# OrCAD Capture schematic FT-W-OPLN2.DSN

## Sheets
1 INDEX: size A; title: INDEX; rev: 1.0; note: ?
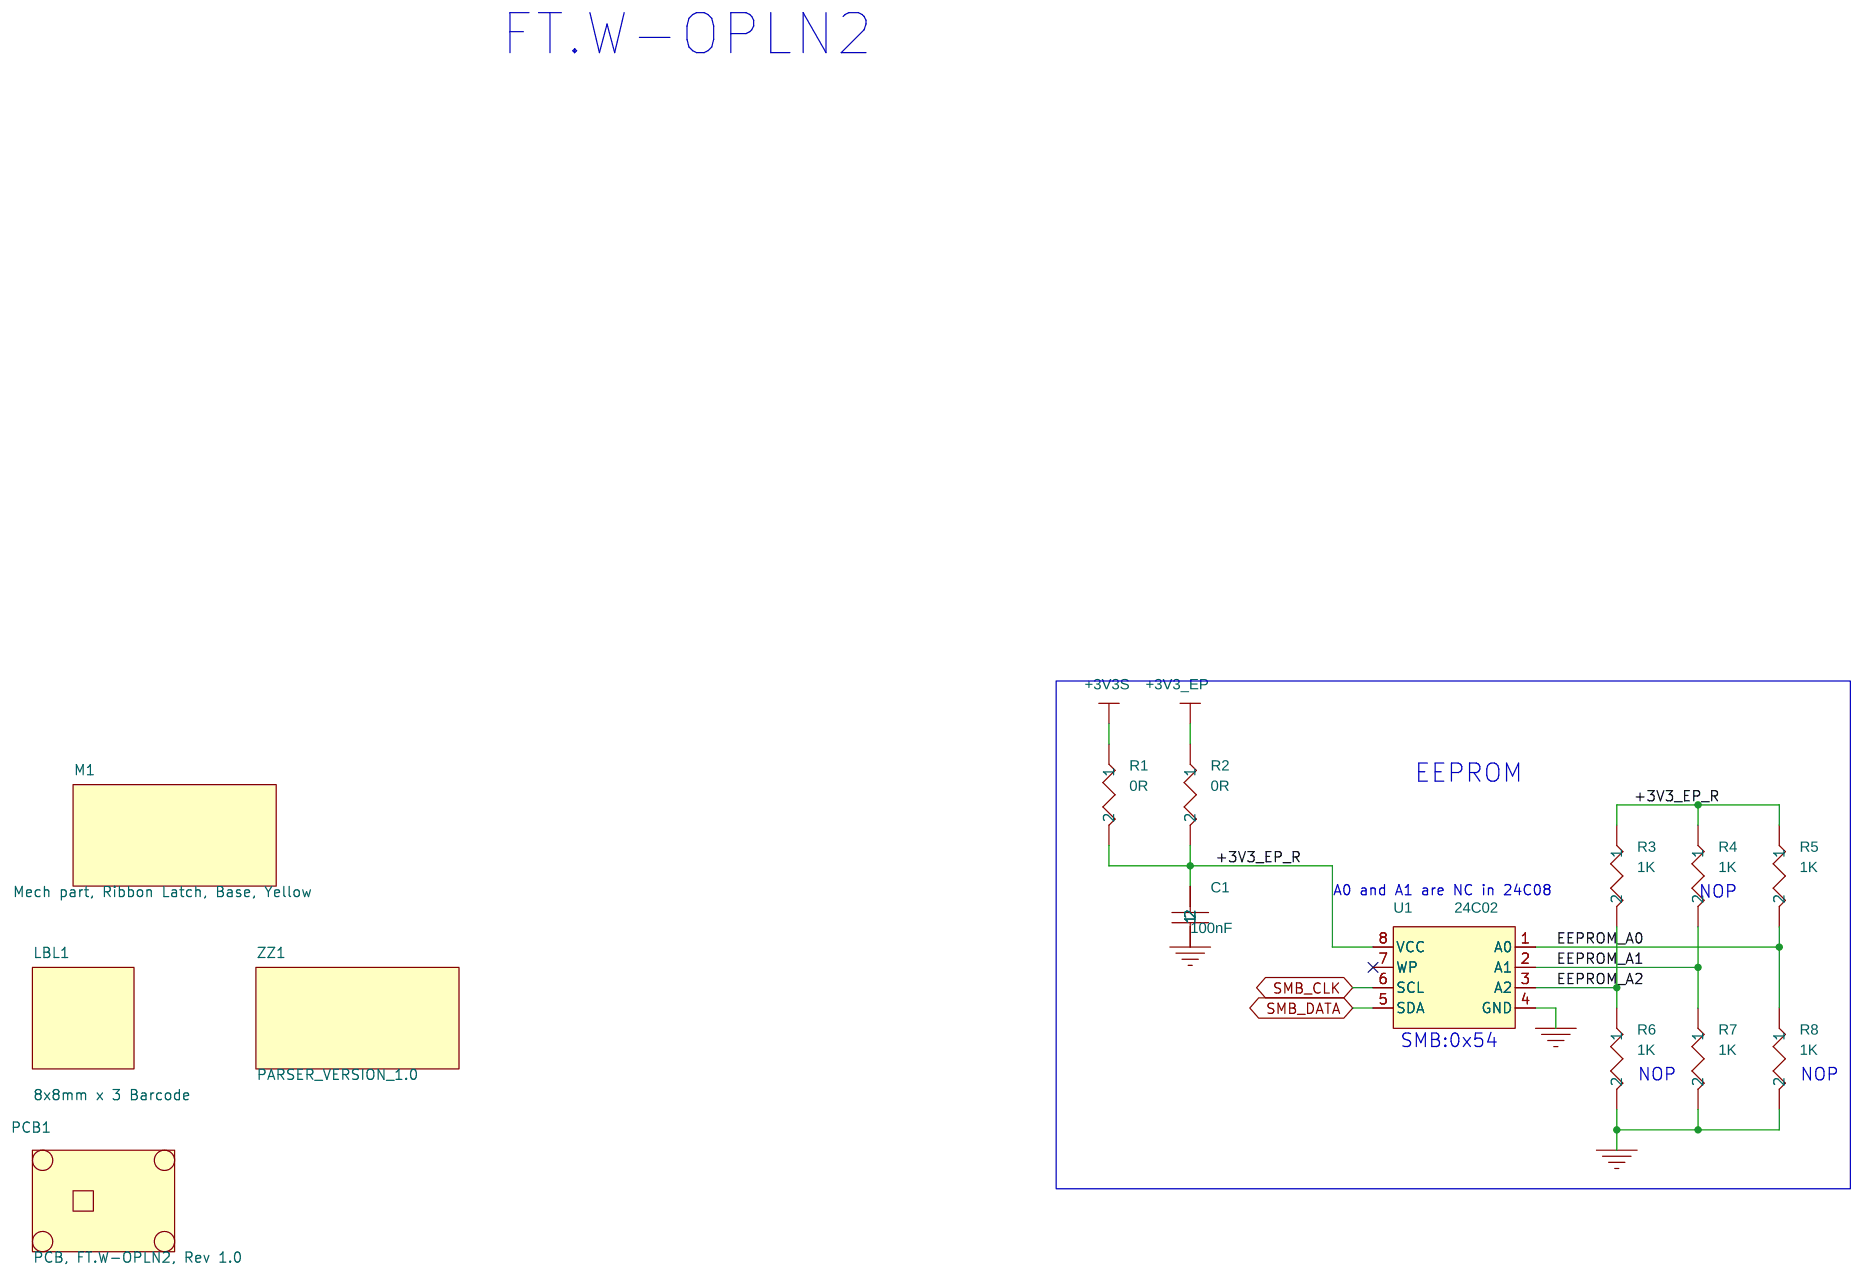
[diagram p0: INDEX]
2 Ribbon Conn.: size B; title: Ribbon Conn
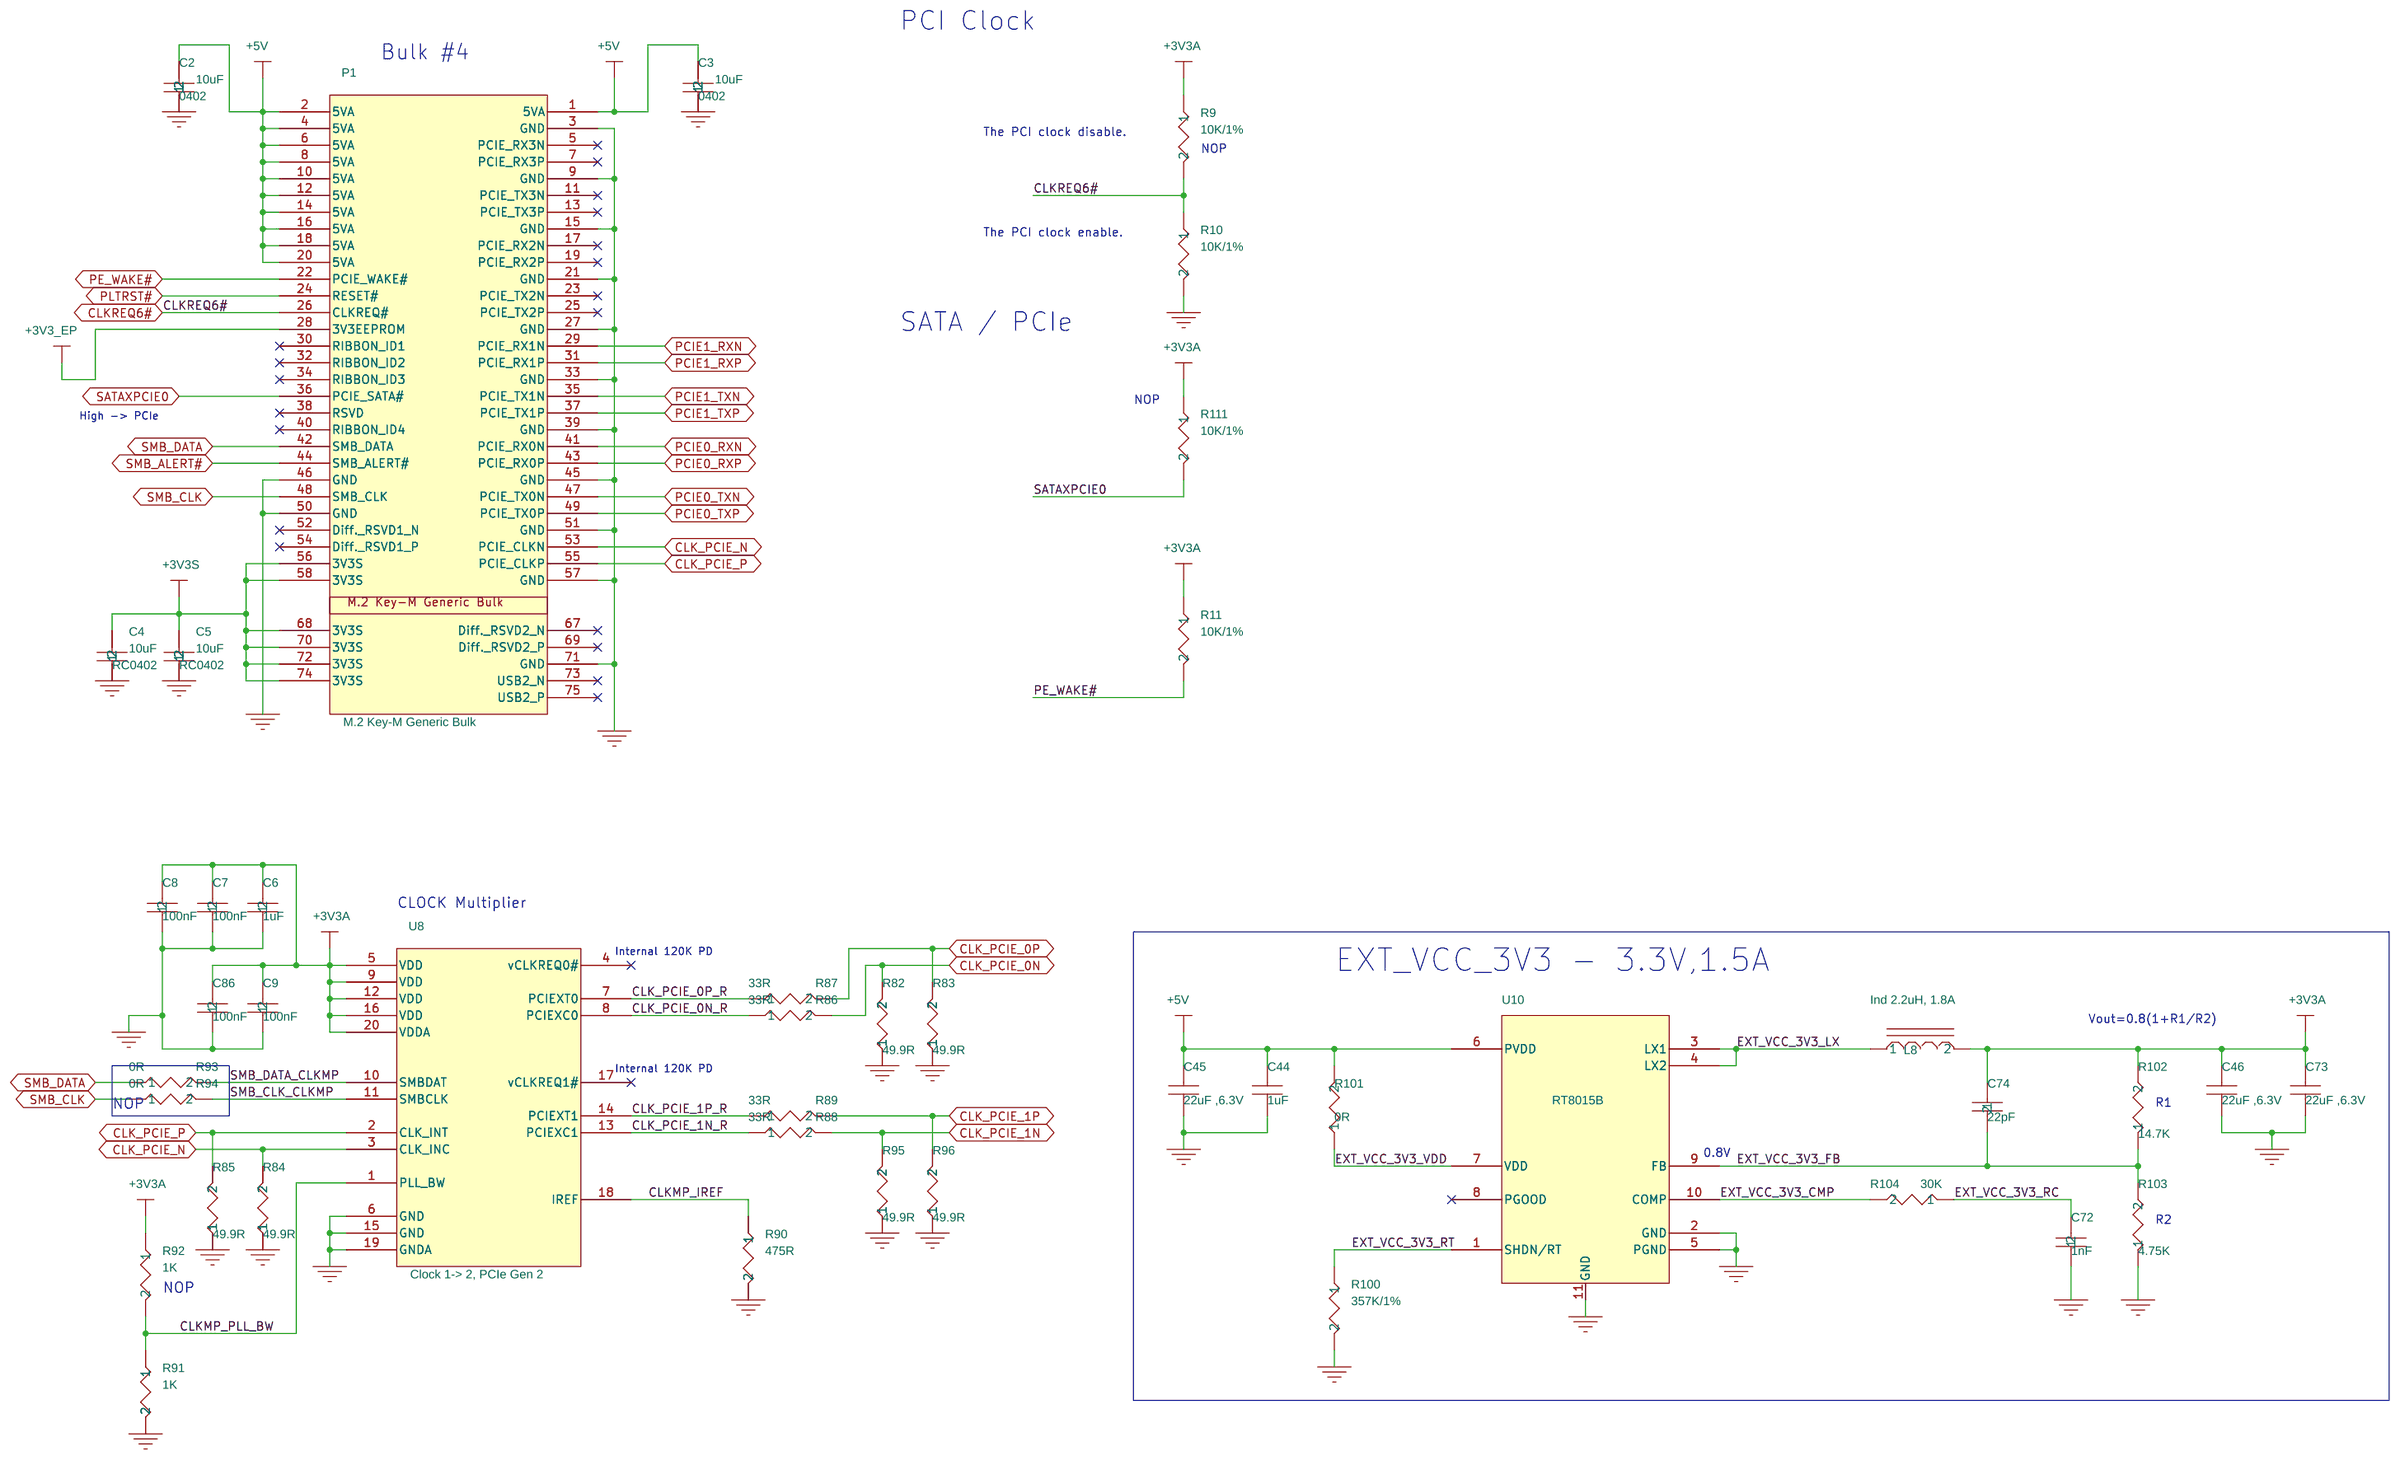
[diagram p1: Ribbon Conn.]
3 OPLN1: size Custom; title: OPLN1
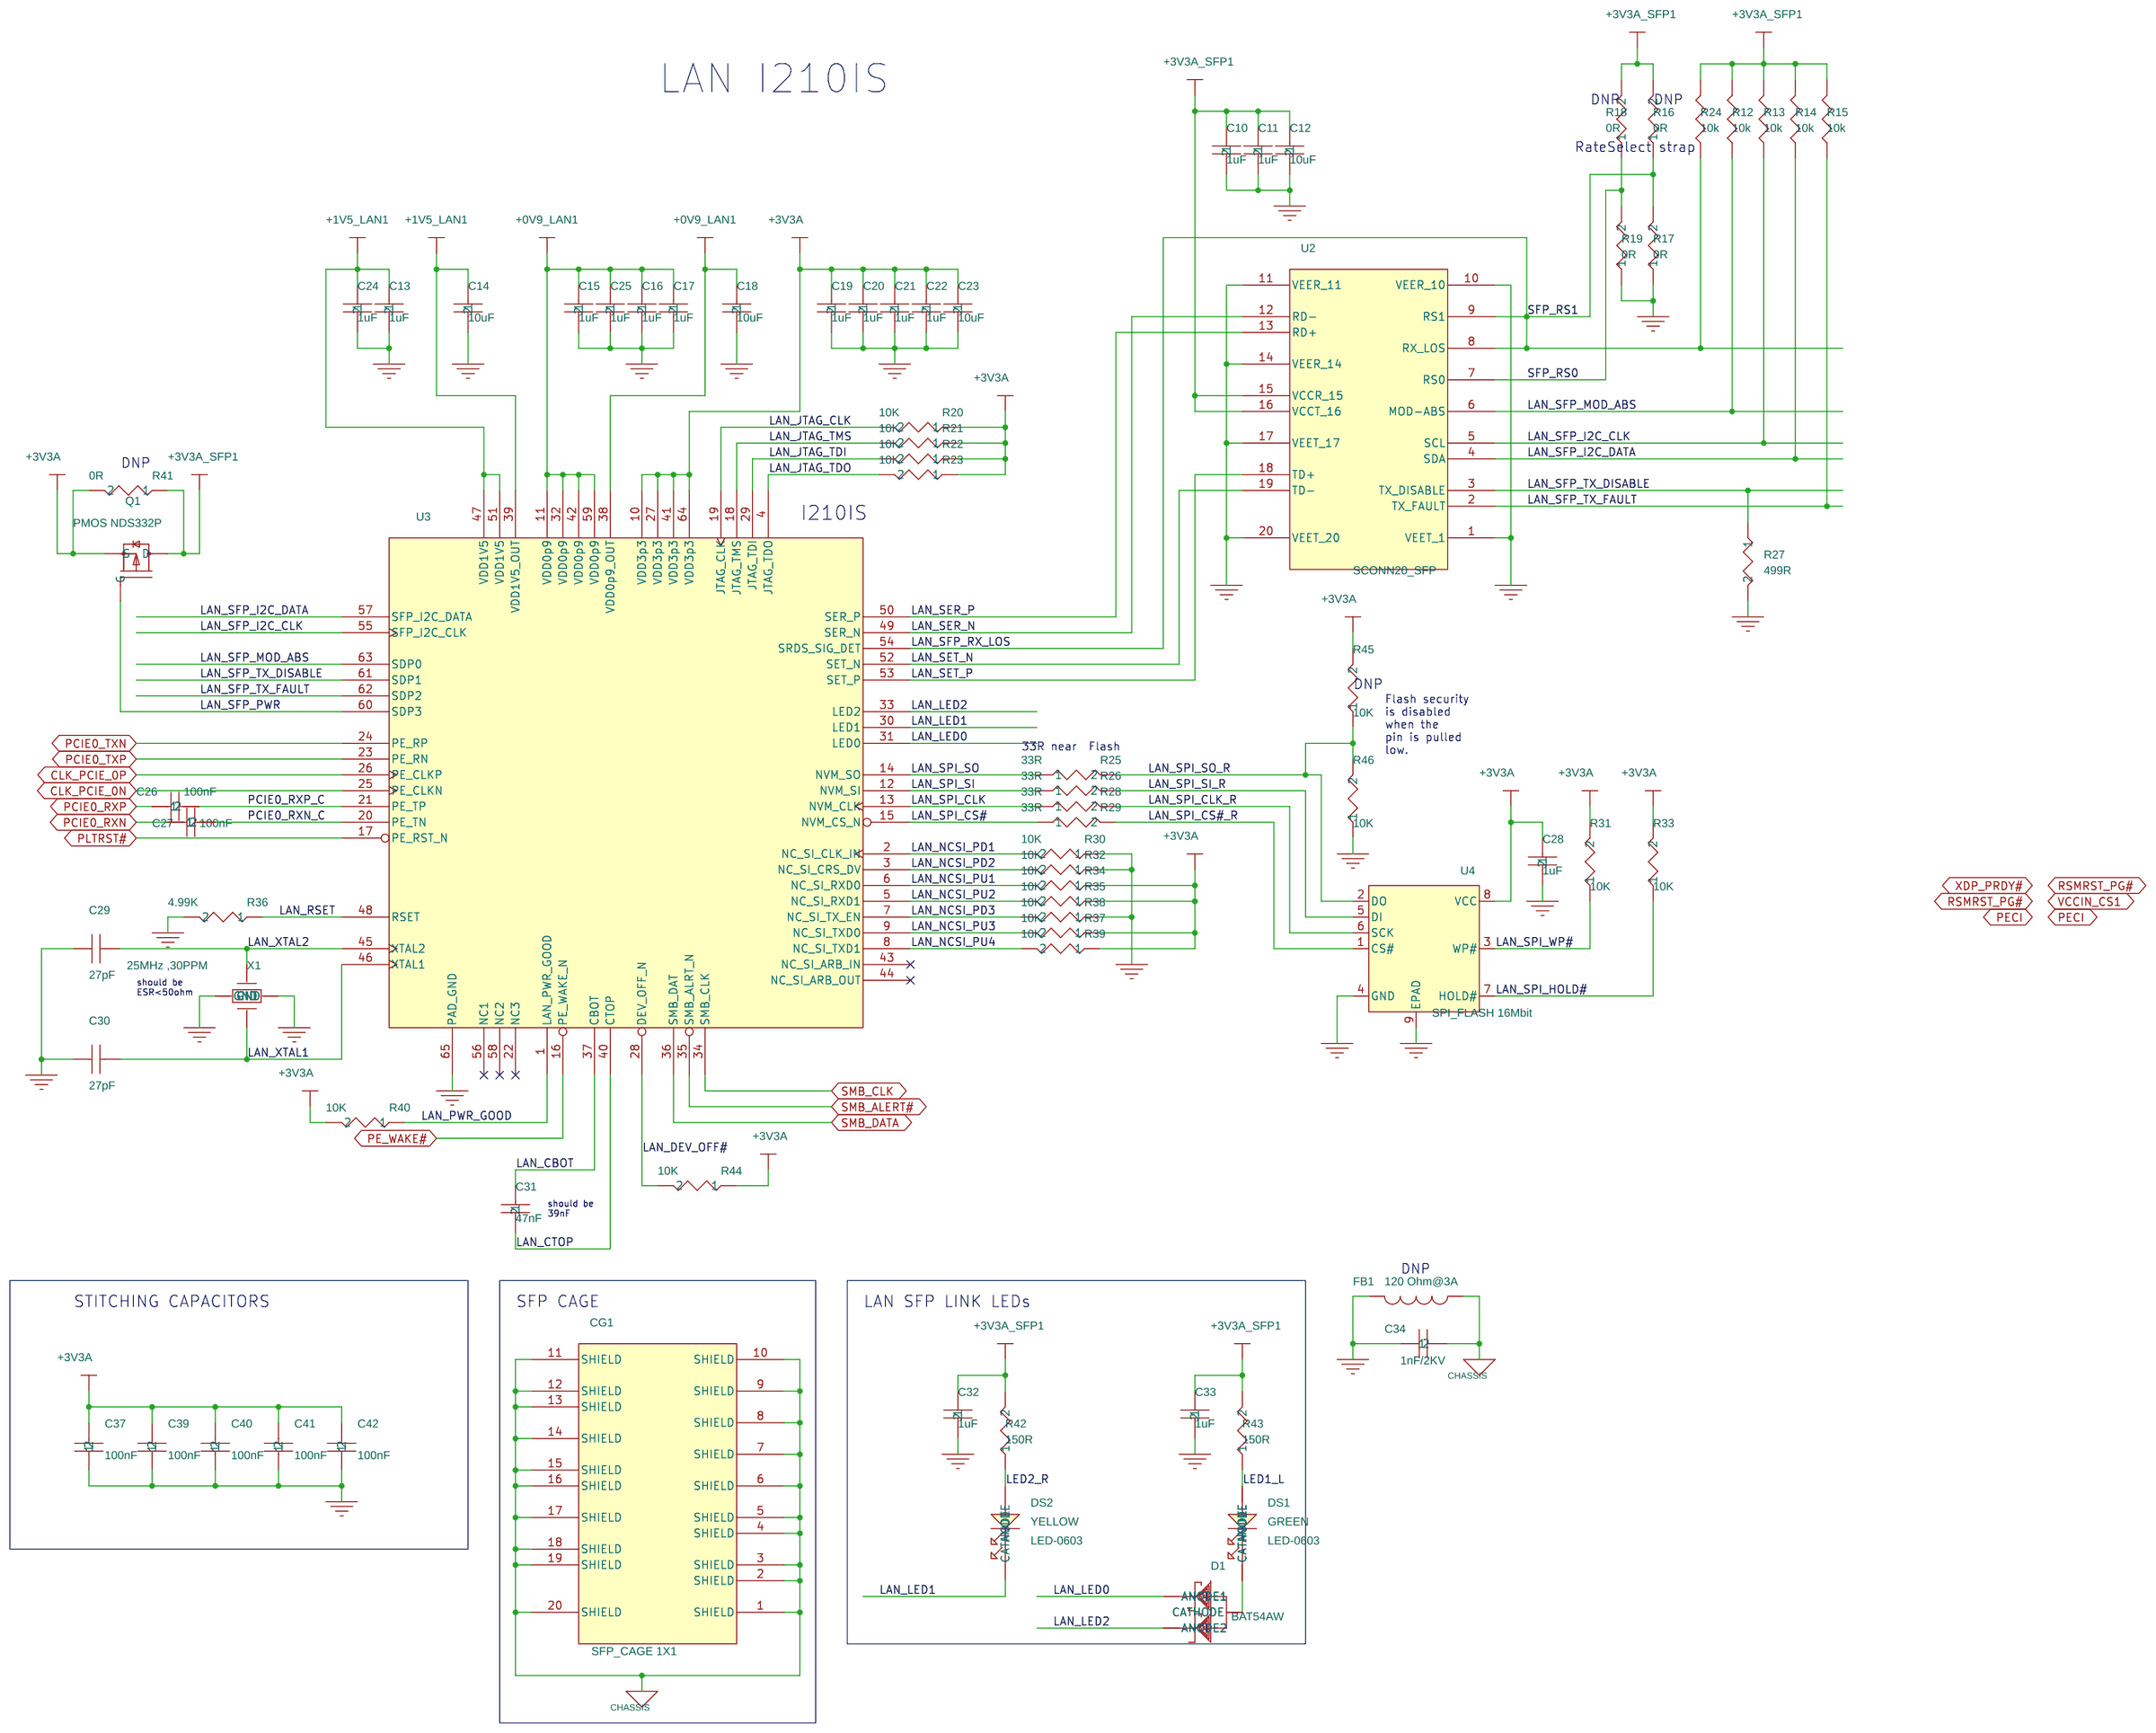
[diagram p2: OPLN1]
4 OPLN2: size Custom; title: OPLN2
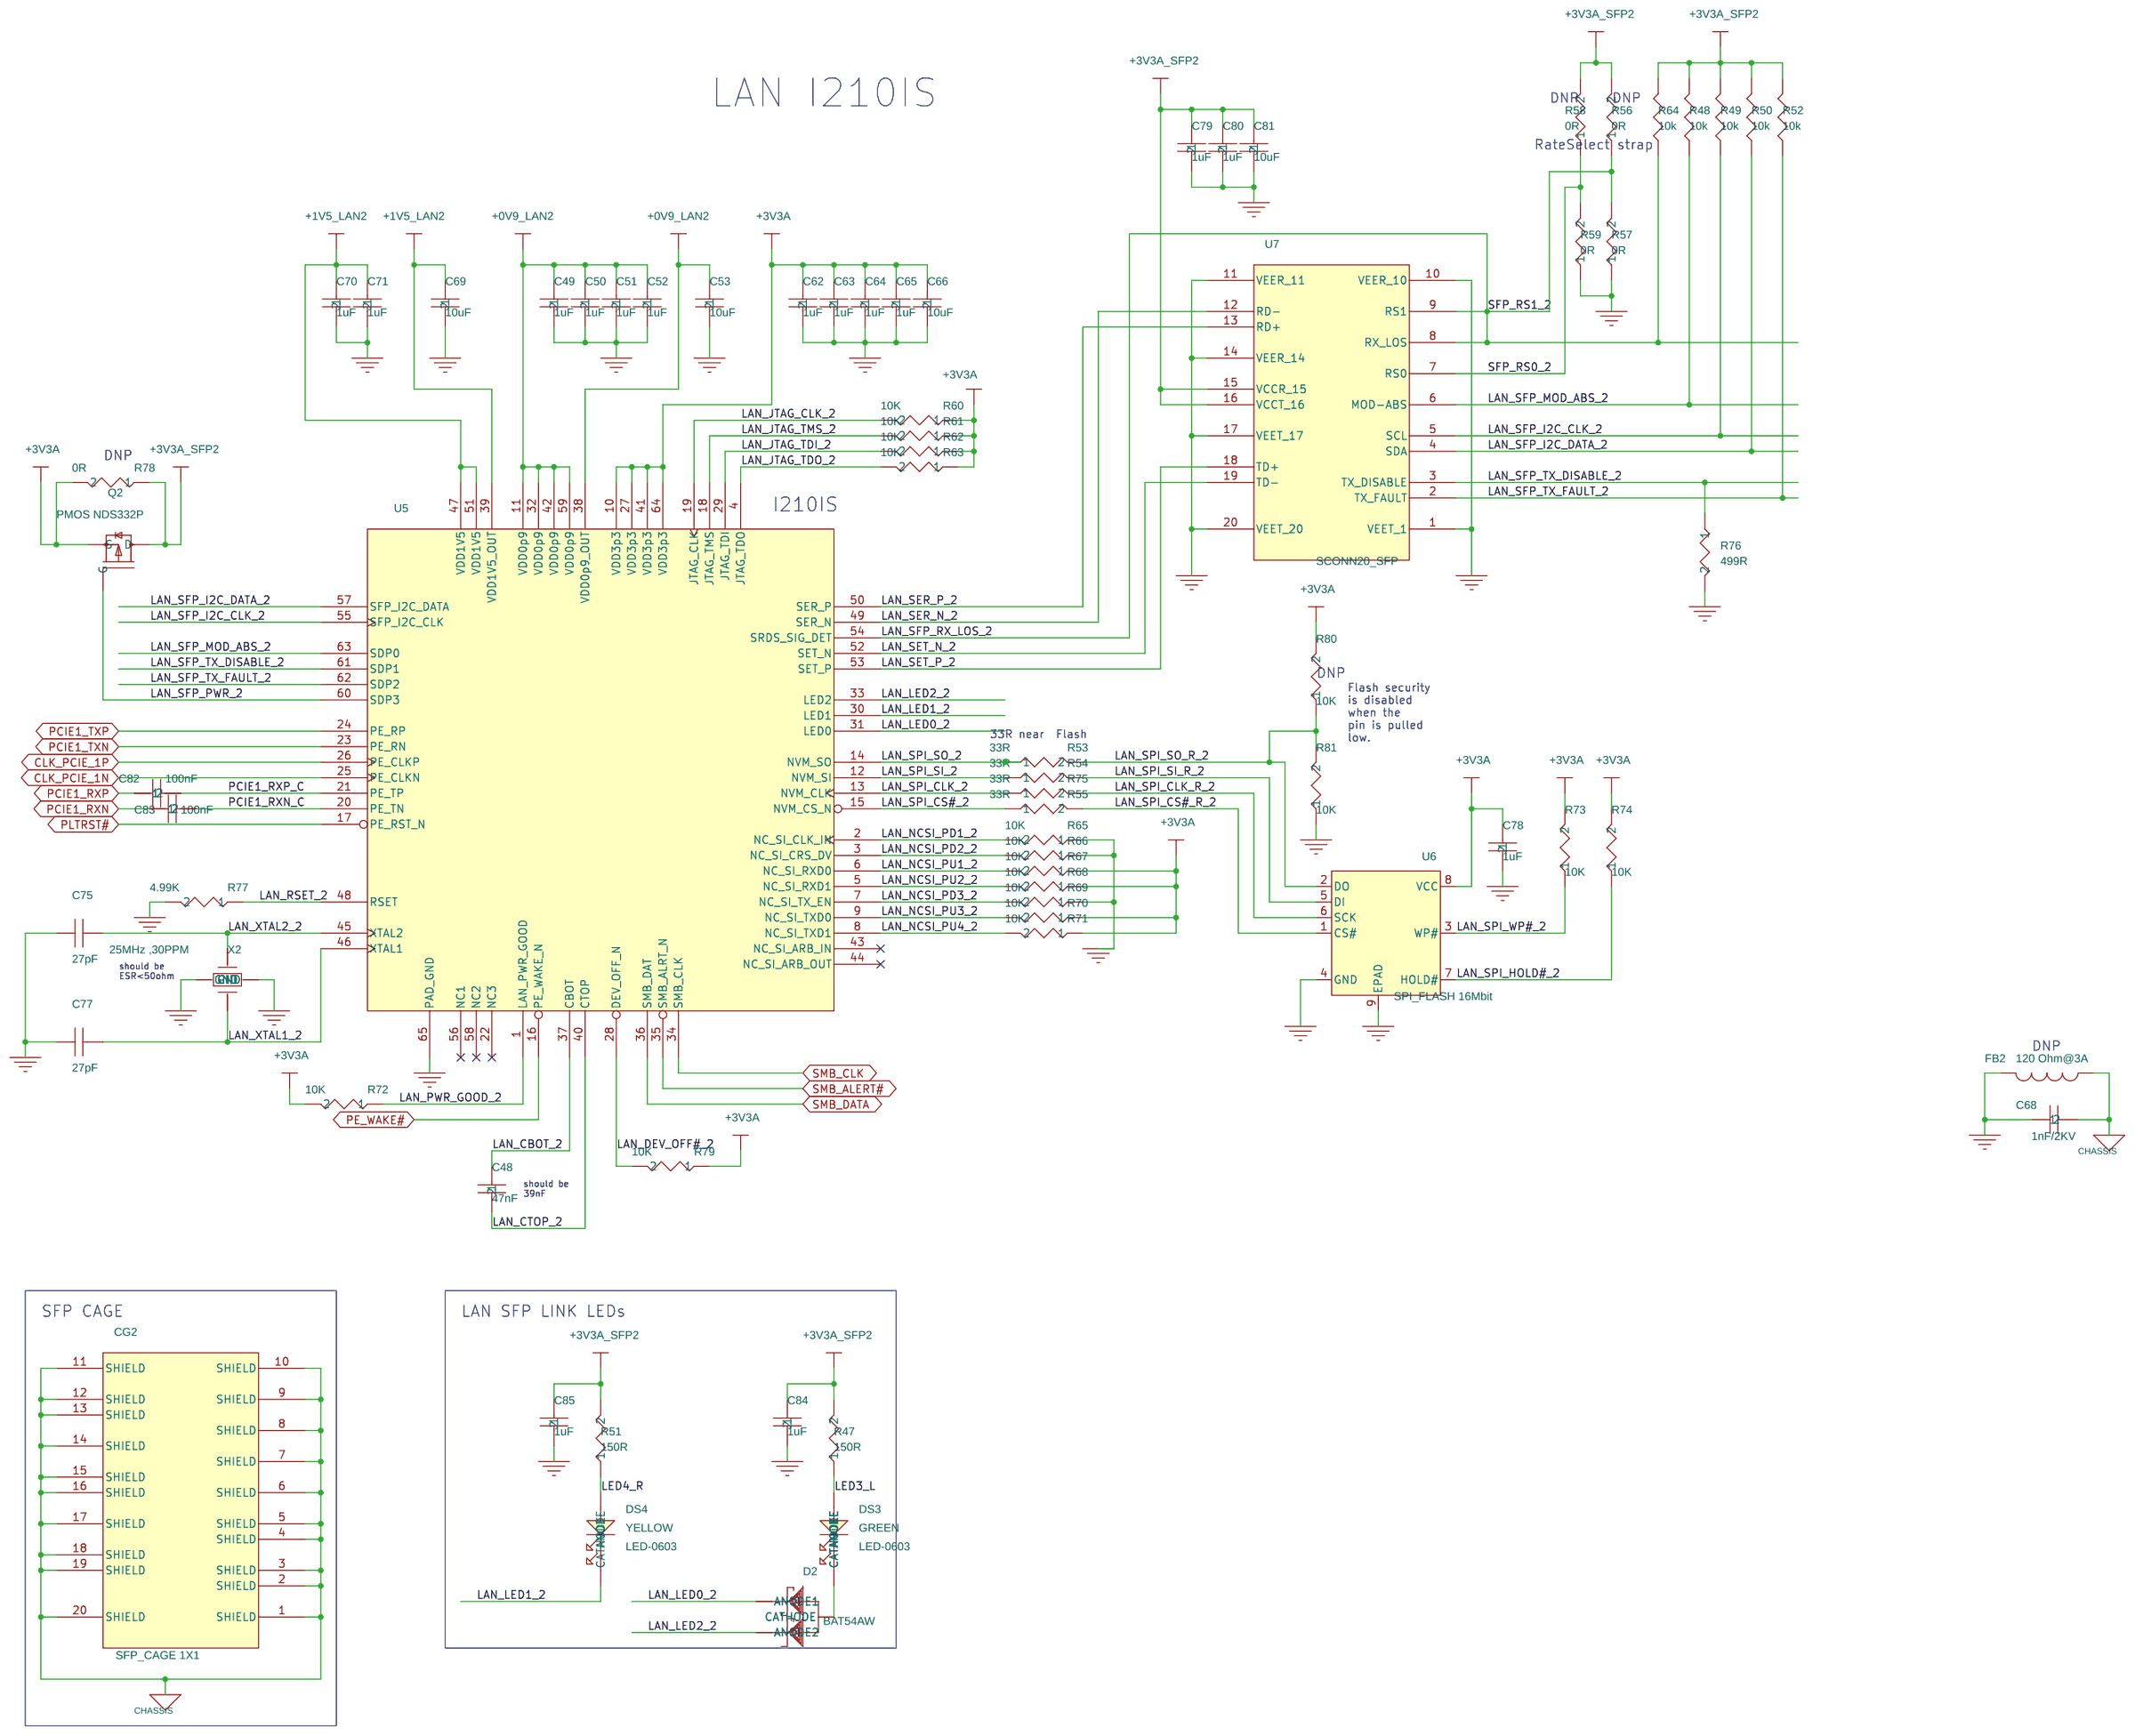
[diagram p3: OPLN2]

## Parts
sheet INDEX
C1  100nF  [RC0402]
LBL1  8x8mm x 3 Barcode  [LBL XYU]
M1  Mech part, Ribbon Latch, Base, Yellow
PCB1  PCB, FT.W-OPLN2, Rev 1.0
R1  0R  [RC0402]
R2  0R  [RC0402]
R3  1K  [RC0402]
R4  1K  [RC0402]
R5  1K  [RC0402]
R6  1K  [RC0402]
R7  1K  [RC0402]
R8  1K  [RC0402]
U1  24C02  [MO-229VCED-2]
ZZ1  PARSER_VERSION_1.0
sheet OPLN1
C10  1uF  [RC0603]
C11  1uF  [RC0603]
C12  10uF  [RC0603]
C13  1uF  [RC0603]
C14  10uF  [RC0603]
C15  1uF  [RC0603]
C16  1uF  [RC0603]
C17  1uF  [RC0603]
C18  10uF  [RC0603]
C19  1uF  [RC0603]
C20  1uF  [RC0603]
C21  1uF  [RC0603]
C22  1uF  [RC0603]
C23  10uF  [RC0603]
C24  1uF  [RC0603]
C25  1uF  [RC0603]
C26  100nF  [RC0402]
C27  100nF  [RC0402]
C28  1uF  [RC0603]
C29  27pF  [RC0402]
C30  27pF  [RC0402]
C31  47nF  [RC0603]
C32  1uF  [RC0603]
C33  1uF  [RC0603]
C34  1nF/2KV  [C1812]
C37  100nF  [RC0402]
C39  100nF  [RC0402]
C40  100nF  [RC0402]
C41  100nF  [RC0402]
C42  100nF  [RC0402]
CG1  SFP_CAGE 1X1
D1  BAT54AW  [SOT323]
DS1  GREEN  [LED-0603]
DS2  YELLOW  [LED-0603]
FB1  120 Ohm@3A  [1206]
Q1  PMOS NDS332P  [SOT23]
R12  10k  [RC0402]
R13  10k  [RC0402]
R14  10k  [RC0402]
R15  10k  [RC0402]
R16  0R  [RC0402]
R17  0R  [RC0402]
R18  0R  [RC0402]
R19  0R  [RC0402]
R20  10K  [RC0402]
R21  10K  [RC0402]
R22  10K  [RC0402]
R23  10K  [RC0402]
R24  10k  [RC0402]
R25  33R  [RC0402]
R26  33R  [RC0402]
R27  499R  [RC0402]
R28  33R  [RC0402]
R29  33R  [RC0402]
R30  10K  [RC0402]
R31  10K  [RC0402]
R32  10K  [RC0402]
R33  10K  [RC0402]
R34  10K  [RC0402]
R35  10K  [RC0402]
R36  4.99K  [RC0402]
R37  10K  [RC0402]
R38  10K  [RC0402]
R39  10K  [RC0402]
R40  10K  [RC0402]
R41  0R  [RC0402]
R42  150R  [RC0402]
R43  150R  [RC0402]
R44  10K  [RC0402]
R45  10K  [RC0402]
R46  10K  [RC0402]
U2  SCONN20_SFP  [SFP_CONN]
U3  WGI210IS
U4  SPI_FLASH 16Mbit  [WSON5x6-8]
X1  25MHz ,30PPM  [OSC3225]
sheet OPLN2
C48  47nF  [RC0603]
C49  1uF  [RC0603]
C50  1uF  [RC0603]
C51  1uF  [RC0603]
C52  1uF  [RC0603]
C53  10uF  [RC0603]
C62  1uF  [RC0603]
C63  1uF  [RC0603]
C64  1uF  [RC0603]
C65  1uF  [RC0603]
C66  10uF  [RC0603]
C68  1nF/2KV  [C1812]
C69  10uF  [RC0603]
C70  1uF  [RC0603]
C71  1uF  [RC0603]
C75  27pF  [RC0402]
C77  27pF  [RC0402]
C78  1uF  [RC0603]
C79  1uF  [RC0603]
C80  1uF  [RC0603]
C81  10uF  [RC0603]
C82  100nF  [RC0402]
C83  100nF  [RC0402]
C84  1uF  [RC0603]
C85  1uF  [RC0603]
CG2  SFP_CAGE 1X1
D2  BAT54AW  [SOT323]
DS3  GREEN  [LED-0603]
DS4  YELLOW  [LED-0603]
FB2  120 Ohm@3A  [1206]
Q2  PMOS NDS332P  [SOT23]
R47  150R  [RC0402]
R48  10k  [RC0402]
R49  10k  [RC0402]
R50  10k  [RC0402]
R51  150R  [RC0402]
R52  10k  [RC0402]
R53  33R  [RC0402]
R54  33R  [RC0402]
R55  33R  [RC0402]
R56  0R  [RC0402]
R57  0R  [RC0402]
R58  0R  [RC0402]
R59  0R  [RC0402]
R60  10K  [RC0402]
R61  10K  [RC0402]
R62  10K  [RC0402]
R63  10K  [RC0402]
R64  10k  [RC0402]
R65  10K  [RC0402]
R66  10K  [RC0402]
R67  10K  [RC0402]
R68  10K  [RC0402]
R69  10K  [RC0402]
R70  10K  [RC0402]
R71  10K  [RC0402]
R72  10K  [RC0402]
R73  10K  [RC0402]
R74  10K  [RC0402]
R75  33R  [RC0402]
R76  499R  [RC0402]
R77  4.99K  [RC0402]
R78  0R  [RC0402]
R79  10K  [RC0402]
R80  10K  [RC0402]
R81  10K  [RC0402]
U5  WGI210IS
U6  SPI_FLASH 16Mbit  [WSON5x6-8]
U7  SCONN20_SFP  [SFP_CONN]
X2  25MHz ,30PPM  [OSC3225]
sheet Ribbon Conn.
C2  10uF  [0402]
C3  10uF  [0402]
C4  10uF  [RC0402]
C5  10uF  [RC0402]
C6  1uF  [RC0402]
C7  100nF  [RC0402]
C8  100nF  [RC0402]
C9  100nF  [RC0402]
C44  1uF  [RC0402]
C45  22uF ,6.3V  [RC0603]
C46  22uF ,6.3V  [RC0603]
C72  1nF  [RC0402]
C73  22uF ,6.3V  [RC0603]
C74  22pF  [RC0402]
C86  100nF  [RC0402]
L8  Ind 2.2uH, 1.8A  [Ind2x2_5x1_2]
P1  M.2 Key-M Generic Bulk  [NGFF67P8HMkeySM]
R9  10K/1%  [RC0402]
R10  10K/1%  [RC0402]
R11  10K/1%  [RC0402]
R82  49.9R  [RC0402]
R83  49.9R  [RC0402]
R84  49.9R  [RC0402]
R85  49.9R  [RC0402]
R86  33R  [RC0402]
R87  33R  [RC0402]
R88  33R  [RC0402]
R89  33R  [RC0402]
R90  475R  [RC0402]
R91  1K  [RC0402]
R92  1K  [RC0402]
R93  0R  [RC0402]
R94  0R  [RC0402]
R95  49.9R  [RC0402]
R96  49.9R  [RC0402]
R100  357K/1%  [RC0402]
R101  0R  [RC0402]
R102  14.7K  [RC0402]
R103  4.75K  [RC0402]
R104  30K  [RC0402]
R111  10K/1%  [RC0402]
U8  Clock 1-> 2, PCIe Gen 2  [TSSOP-20]
U10  RT8015B  [DFN3x3-10]

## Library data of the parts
C1 C86 = 15pF,_50V,_NPO,_5%,_0402: CLABCONF0: =FT-W-OPLN2; P/N: 151B10400S
LBL1 = Label_8x8mm_x_3_for_Barcode: CLABCONF0: =FT-W-OPLN2
M1 = PARSER_VERSION_1_0.0: CLABCONF0: =FT-W-OPLN2; P/N: 290E010010
PCB1 = SBC-iHSW_Rev_1.0: CLABCONF0: =FT-W-OPLN2; P/N: 188C03620U
R1 = 348R,1%,0402,1_16W_7: CLABCONF0: =NOP; P/N: 161C00005S
R2 = 348R,1%,0402,1_16W_6: CLABCONF0: =FT-W-OPLN2; P/N: 161C00005S
R3 = 348R,1%,0402,1_16W_5: CLABCONF0: =FT-W-OPLN2; P/N: 161C10011S
R4 = 348R,1%,0402,1_16W_4: CLABCONF0: =NOP; P/N: 161C10011S
R5 = 348R,1%,0402,1_16W_2: CLABCONF0: =NOP; P/N: 161C10011S
R6 = 348R,1%,0402,1_16W: CLABCONF0: =NOP; P/N: 161C10011S
R7 = 348R,1%,0402,1_16W_3: CLABCONF0: =NOP; P/N: 161C10011S
R8 = 348R,1%,0402,1_16W_1: CLABCONF0: =NOP; P/N: 161C10011S
U1 = 24C02,_serial_EE,_2KB,_I2C: CLABCONF0: =FT-W-OPLN2; P/N: 111S30801S
ZZ1 = PARSER_VERSION_1.0: CLABCONF0: =FT-W-OPLN2
C10 C80 = 47nF,_25V,_X7R,_10%,_0603_12: CLABCONF0: =FT-W-OPLN2; P/N: 151C10500S
C11 C70 = 47nF,_25V,_X7R,_10%,_0603_17: CLABCONF0: =FT-W-OPLN2; P/N: 151C10500S
C12 = 47nF,_25V,_X7R,_10%,_0603_8: CLABCONF0: =FT-W-OPLN2; P/N: 151B10600S
C13 C52 = 47nF,_25V,_X7R,_10%,_0603_6: CLABCONF0: =FT-W-OPLN2; P/N: 151C10500S
C14 = 47nF,_25V,_X7R,_10%,_0603_14: CLABCONF0: =FT-W-OPLN2; P/N: 151B10600S
C15 C65 = 47nF,_25V,_X7R,_10%,_0603_7: CLABCONF0: =FT-W-OPLN2; P/N: 151C10500S
C16 C63 = 47nF,_25V,_X7R,_10%,_0603_18: CLABCONF0: =FT-W-OPLN2; P/N: 151C10500S
C17 = 47nF,_25V,_X7R,_10%,_0603_10: CLABCONF0: =FT-W-OPLN2; P/N: 151C10500S
C18 = 47nF,_25V,_X7R,_10%,_0603: CLABCONF0: =FT-W-OPLN2; P/N: 151B10600S
C19 C84 = 47nF,_25V,_X7R,_10%,_0603_9: CLABCONF0: =FT-W-OPLN2; P/N: 151C10500S
C20 C49 = 47nF,_25V,_X7R,_10%,_0603_2: CLABCONF0: =FT-W-OPLN2; P/N: 151C10500S
C21 C85 = 47nF,_25V,_X7R,_10%,_0603_15: CLABCONF0: =FT-W-OPLN2; P/N: 151C10500S
C22 C64 = 47nF,_25V,_X7R,_10%,_0603_11: CLABCONF0: =FT-W-OPLN2; P/N: 151C10500S
C23 C53 = 47nF,_25V,_X7R,_10%,_0603_16: CLABCONF0: =FT-W-OPLN2; P/N: 151B10600S
C24 C78 = 47nF,_25V,_X7R,_10%,_0603_1: CLABCONF0: =FT-W-OPLN2; P/N: 151C10500S
C25 = 47nF,_25V,_X7R,_10%,_0603_4: CLABCONF0: =FT-W-OPLN2; P/N: 151C10500S
C26 C83 = 100nF,_10V,_X7R,_10%,_0402_1: CLABCONF0: =FT-W-OPLN2
C27 = 100nF,_10V,_X7R,_10%,_0402_4: CLABCONF0: =FT-W-OPLN2
C28 C62 = 47nF,_25V,_X7R,_10%,_0603_5: CLABCONF0: =FT-W-OPLN2; P/N: 151C10500S
C29 C30 C75 C77 = 27pF,_50V,_X7R,_10%,_0402: CLABCONF0: =FT-W-OPLN2; P/N: 151D27000S
C31 = 47nF,_25V,_X7R,_10%,_0603_3: CLABCONF0: =FT-W-OPLN2; P/N: 151C47300S
C32 = 47nF,_25V,_X7R,_10%,_0603_19: CLABCONF0: =FT-W-OPLN2; P/N: 151C10500S
C33 = 47nF,_25V,_X7R,_10%,_0603_13: CLABCONF0: =FT-W-OPLN2; P/N: 151C10500S
C34 C68 = 1nF,_2KV,SMD_1812,_X7R,_10%_0: CLABCONF0: =FT-W-OPLN2
C37 = 100nF,_10V,_X7R,_10%,_0402_3: CLABCONF0: =FT-W-OPLN2
C39 = 100nF,_10V,_X7R,_10%,_0402_6: CLABCONF0: =FT-W-OPLN2
C40 C82 = 100nF,_10V,_X7R,_10%,_0402: CLABCONF0: =FT-W-OPLN2
C41 = 100nF,_10V,_X7R,_10%,_0402_2: CLABCONF0: =FT-W-OPLN2
C42 = 100nF,_10V,_X7R,_10%,_0402_5: CLABCONF0: =FT-W-OPLN2
CG1 CG2 = SFP_CAGE_0: CLABCONF0: =FT-W-OPLN2; P/N: 203H10060
D1 D2 = BAT54AW: CLABCONF0: =E
DS1 DS3 = LED-RED_1206_1: CLABCONF0: SBC-CLH; P/N: 139A10260S
DS2 DS4 = LED-RED_1206: CLABCONF0: SBC-CLH; P/N: 139A10280S
FB1 FB2 = Ferrite_bead_,_120_Ohm@3A_0: CLABCONF0: =NOP
Q1 Q2 = P-MOSFET,3A,20V,110mOhm@-1.8V: CLABCONF0: =FT-W-OPLN2
R12-R15 R24 R48-R50 R52 R64 = 1M_,5%,_0402_0: CLABCONF0: =FT-W-OPLN2; P/N: 161C10021S
R16 = 0R,_0402_0_3: CLABCONF0: =NOP
R17 = 0R,_0402_0_4: CLABCONF0: =FT-W-OPLN2
R18 = 0R,_0402_0: CLABCONF0: =NOP
R19 R78 = 0R,_0402_0_1: CLABCONF0: =FT-W-OPLN2
R20 R79 = 0R_5: CLABCONF0: =FT-W-OPLN2; P/N: 161C10021S
R21 R65 = 0R_4: CLABCONF0: =FT-W-OPLN2; P/N: 161C10021S
R22 = 0R_9: CLABCONF0: =FT-W-OPLN2; P/N: 161C10021S
R23 = 0R_13: CLABCONF0: =FT-W-OPLN2; P/N: 161C10021S
R25 = 0R_15: CLABCONF0: =FT-W-OPLN2; P/N: 161C33R05S
R26 = 0R_2: CLABCONF0: =FT-W-OPLN2; P/N: 161C33R05S
R27 R76 = 75R,1%,0402,1_16W: CLABCONF0: =FT-W-OPLN2; Group: POWER_48; P/N: 161C49901S
R28 = 0R_11: CLABCONF0: =FT-W-OPLN2; P/N: 161C33R05S
R29 = 0R: CLABCONF0: =FT-W-OPLN2; P/N: 161C33R05S
R30 R81 = 0R_7: CLABCONF0: =FT-W-OPLN2; P/N: 161C10021S
R31 = 0R_17: CLABCONF0: =FT-W-OPLN2; P/N: 161C10021S
R32 R74 = 0R_20: CLABCONF0: =FT-W-OPLN2; P/N: 161C10021S
R33 = 0R_22: CLABCONF0: =FT-W-OPLN2; P/N: 161C10021S
R34 R61 = 0R_1: CLABCONF0: =FT-W-OPLN2; P/N: 161C10021S
R35 R67 = 0R_23: CLABCONF0: =FT-W-OPLN2; P/N: 161C10021S
R36 = 0R_21: CLABCONF0: =FT-W-OPLN2; P/N: 161C49911S
R37 R73 = 0R_12: CLABCONF0: =FT-W-OPLN2; P/N: 161C10021S
R38 R71 = 0R_16: CLABCONF0: =FT-W-OPLN2; P/N: 161C10021S
R39 R68 = 0R_19: CLABCONF0: =FT-W-OPLN2; P/N: 161C10021S
R40 = 0R_3: CLABCONF0: =FT-W-OPLN2; P/N: 161C10021S
R41 = 0R,_0402_0_2: CLABCONF0: =FT-W-OPLN2
R42 = 0R_14: CLABCONF0: =FT-W-OPLN2; P/N: 161C15001S
R43 = 0R_18: CLABCONF0: =FT-W-OPLN2; P/N: 161C15001S
R44 = 0R_8: CLABCONF0: =FT-W-OPLN2; P/N: 161C10021S
R45 = 0R_6: CLABCONF0: =NOP; P/N: 161C10021S
R46 R70 = 0R_10: CLABCONF0: =FT-W-OPLN2; P/N: 161C10021S
U2 U7 = SCONN20_SFP: CLABCONF0: =FT-W-OPLN2; P/N: 184K02000S
U3 U5 = I210IS_0: CLABCONF0: =FT-W-OPLN2; P/N: 116B00072S
U4 U6 = IC,FLASH,SPI,64MBit_0: CLABCONF0: =FT-W-OPLN2; P/N: 111S32100I
X1 X2 = TMP_133032: CLABCONF0: =FT-W-OPLN2; P/N: 141B25603I
C48 = 47nF,_25V,_X7R,_10%,_0603_19: CLABCONF0: =FT-W-OPLN2; P/N: 151C47300S
C50 = 47nF,_25V,_X7R,_10%,_0603: CLABCONF0: =FT-W-OPLN2; P/N: 151C10500S
C51 = 47nF,_25V,_X7R,_10%,_0603_14: CLABCONF0: =FT-W-OPLN2; P/N: 151C10500S
C66 = 47nF,_25V,_X7R,_10%,_0603_13: CLABCONF0: =FT-W-OPLN2; P/N: 151B10600S
C69 = 47nF,_25V,_X7R,_10%,_0603_10: CLABCONF0: =FT-W-OPLN2; P/N: 151B10600S
C71 = 47nF,_25V,_X7R,_10%,_0603_3: CLABCONF0: =FT-W-OPLN2; P/N: 151C10500S
C79 = 47nF,_25V,_X7R,_10%,_0603_8: CLABCONF0: =FT-W-OPLN2; P/N: 151C10500S
C81 = 47nF,_25V,_X7R,_10%,_0603_4: CLABCONF0: =FT-W-OPLN2; P/N: 151B10600S
R47 = 0R_15: CLABCONF0: =FT-W-OPLN2; P/N: 161C15001S
R51 = 0R_9: CLABCONF0: =FT-W-OPLN2; P/N: 161C15001S
R53 = 0R_13: CLABCONF0: =FT-W-OPLN2; P/N: 161C33R05S
R54 = 0R_22: CLABCONF0: =FT-W-OPLN2; P/N: 161C33R05S
R55 = 0R_21: CLABCONF0: =FT-W-OPLN2; P/N: 161C33R05S
R56 = 0R,_0402_0_2: CLABCONF0: =NOP
R57 = 0R,_0402_0_3: CLABCONF0: =FT-W-OPLN2
R58 = 0R,_0402_0_4: CLABCONF0: =NOP
R59 = 0R,_0402_0: CLABCONF0: =FT-W-OPLN2
R60 = 0R_2: CLABCONF0: =FT-W-OPLN2; P/N: 161C10021S
R62 = 0R_6: CLABCONF0: =FT-W-OPLN2; P/N: 161C10021S
R63 = 0R_11: CLABCONF0: =FT-W-OPLN2; P/N: 161C10021S
R66 = 0R_18: CLABCONF0: =FT-W-OPLN2; P/N: 161C10021S
R69 = 0R_14: CLABCONF0: =FT-W-OPLN2; P/N: 161C10021S
R72 = 0R: CLABCONF0: =FT-W-OPLN2; P/N: 161C10021S
R75 = 0R_8: CLABCONF0: =FT-W-OPLN2; P/N: 161C33R05S
R77 = 0R_17: CLABCONF0: =FT-W-OPLN2; P/N: 161C49911S
R80 = 0R_3: CLABCONF0: =NOP; P/N: 161C10021S
C2 = 100nF,_10V,_X7R,_10%,_0402_4: CLABCONF0: =FT-W-OPLN2; P/N: 151B10600S
C3 = 100nF,_10V,_X7R,_10%,_0402_1: CLABCONF0: =FT-W-OPLN2; P/N: 151B10600S
C4 = 100nF,_10V,_X7R,_10%,_0402_2: CLABCONF0: =FT-W-OPLN2; P/N: 151B10600S
C5 = 100nF,_10V,_X7R,_10%,_0402: CLABCONF0: =FT-W-OPLN2; P/N: 151B10600S
C6 = 100nF,_10V,_X7R,_10%,_0402_3: CLABCONF0: =FT-W-OPLN2; P/N: 151C10500S
C7 = 15pF,_50V,_NPO,_5%,_0402_3: CLABCONF0: =FT-W-OPLN2; P/N: 151B10400S
C8 = 15pF,_50V,_NPO,_5%,_0402_2: CLABCONF0: =FT-W-OPLN2; P/N: 151B10400S
C9 = 15pF,_50V,_NPO,_5%,_0402_1: CLABCONF0: =FT-W-OPLN2; P/N: 151B10400S
C44 = 1uF,X5R,6.3V,0402: CLABCONF0: =FT-W-OPLN2; P/N: 151B105B0S
C45 = 22uF,6.3V,X5R: CLABCONF0: =FT-W-OPLN2; P/N: 151B22610S
C46 = 22uF,6.3V,X5R_1: CLABCONF0: =FT-W-OPLN2; P/N: 151B22610S
C72 = 1nF,10%,_50V,_X7R,_0402: CLABCONF0: =FT-W-OPLN2
C73 = 22uF,6.3V,X5R_2: CLABCONF0: =FT-W-OPLN2; P/N: 151B22610S
C74 = 22pF,_50V,_NPO,_5%,_0402: CLABCONF0: =FT-W-OPLN2
L8 = Ind_micro_2R2-2.2uH_@_1.8A: CLABCONF0: =FT-W-OPLN2
P1 = M.2_Key-M_Generic_Bulk: CLABCONF0: =FT-W-OPLN2; P/N: 182K06700S
R9 = 10K,1%,0402,1_16W_2: CLABCONF0: =NOP
R10 = 10K,1%,0402,1_16W_1: CLABCONF0: =FT-W-OPLN2
R11 = 10K,1%,0402,1_16W: CLABCONF0: =FT-W-OPLN2
R82 = 348R,1%,0402,1_16W_9: CLABCONF0: =FT-W-OPLN2; P/N: 161C49R91S
R83 = 348R,1%,0402,1_16W_8: CLABCONF0: =FT-W-OPLN2; P/N: 161C49R91S
R84 = 348R,1%,0402,1_16W_7: CLABCONF0: =FT-W-OPLN2; P/N: 161C49R91S
R85 = 348R,1%,0402,1_16W_6: CLABCONF0: =FT-W-OPLN2; P/N: 161C49R91S
R86 = 348R,1%,0402,1_16W_4: CLABCONF0: =FT-W-OPLN2; P/N: 161C33R05S
R87 = 348R,1%,0402,1_16W_2: CLABCONF0: =FT-W-OPLN2; P/N: 161C33R05S
R88 = 348R,1%,0402,1_16W: CLABCONF0: =FT-W-OPLN2; P/N: 161C33R05S
R89 = 348R,1%,0402,1_16W_14: CLABCONF0: =FT-W-OPLN2; P/N: 161C33R05S
R90 = 348R,1%,0402,1_16W_13: CLABCONF0: =FT-W-OPLN2; P/N: 161C47501S
R91 = 348R,1%,0402,1_16W_12: CLABCONF0: =FT-W-OPLN2; P/N: 161C10011S
R92 = 348R,1%,0402,1_16W_11: CLABCONF0: =NOP; P/N: 161C10011S
R93 = 348R,1%,0402,1_16W_5: CLABCONF0: =NOP; P/N: 161C00005S
R94 = 348R,1%,0402,1_16W_10: CLABCONF0: =NOP; P/N: 161C00005S
R95 = 348R,1%,0402,1_16W_3: CLABCONF0: =FT-W-OPLN2; P/N: 161C49R91S
R96 = 348R,1%,0402,1_16W_1: CLABCONF0: =FT-W-OPLN2; P/N: 161C49R91S
R100 = 357K,1%,0402,1_16W: CLABCONF0: =FT-W-OPLN2
R101 = 0R,_0402: CLABCONF0: =FT-W-OPLN2
R102 = 100K,_0402_2: CLABCONF0: =FT-W-OPLN2; P/N: 161C14721S
R103 = 100K,_0402_1: CLABCONF0: =FT-W-OPLN2; P/N: 161C47511S
R104 = 100K,_0402: CLABCONF0: =FT-W-OPLN2; P/N: 161C30021S
R111 = 10K,1%,0402,1_16W_3: CLABCONF0: =FT-W-OPLN2
U8 = Clock_1-__2,_PCIe_Gen_2: CLABCONF0: =FT-W-OPLN2; P/N: 106IA1010S
U10 = RT8051B_4: CLABCONF0: =FT-W-OPLN2; P/N: 123V5R004S

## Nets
+0V9_LAN1: C15.1 C16.1 C17.1 C18.1 C25.1 U3.11(VDD0p9) U3.32(VDD0p9) U3.38(VDD0p9_OUT) U3.42(VDD0p9) U3.59(VDD0p9)
+0V9_LAN2: C49.1 C50.1 C51.1 C52.1 C53.1 U5.11(VDD0p9) U5.32(VDD0p9) U5.38(VDD0p9_OUT) U5.42(VDD0p9) U5.59(VDD0p9)
+1V5_LAN1: C13.1 C14.1 C24.1 U3.39(VDD1V5_OUT) U3.47(VDD1V5) U3.51(VDD1V5)
+1V5_LAN2: C69.1 C70.1 C71.1 U5.39(VDD1V5_OUT) U5.47(VDD1V5) U5.51(VDD1V5)
+3V3_EP: P1.28(3V3EEPROM) R2.1
+3V3_EP_R: C1.2 R1.2 R2.2 R3.1 R4.1 R5.1 U1.8(VCC)
+3V3A: C6.2 C7.2 C8.2 C9.2 C19.1 C20.1 C21.1 C22.1 C23.1 C28.1 C37.2 C39.2 C40.2 C41.2 C42.2 C46.1 C62.1 C63.1 C64.1 C65.1 C66.1 C73.1 C74.1 C78.1 C86.2 L8.2 Q1.2(S) Q2.2(S) R9.1 R11.1 R20.1 R21.1 R22.1 R23.1 R31.2 R33.2 R34.1 R35.1 R37.1 R39.1 R40.2 R41.2 R44.1 R45.2 R60.1 R61.1 R62.1 R63.1 R67.1 R68.1 R70.1 R71.1 R72.2 R73.2 R74.2 R78.2 R79.1 R80.2 R92.1 R102.2 R111.1 U3.10(VDD3p3) U3.27(VDD3p3) U3.41(VDD3p3) U3.64(VDD3p3) U4.8(VCC) U5.10(VDD3p3) U5.27(VDD3p3) U5.41(VDD3p3) U5.64(VDD3p3) U6.8(VCC) U8.5(VDD) U8.9(VDD) U8.12(VDD) U8.16(VDD) U8.20(VDDA)
+3V3A_SFP1: C10.1 C11.1 C12.1 C32.1 C33.1 Q1.3(D) R12.2 R13.2 R14.2 R15.2 R16.2 R18.2 R24.2 R41.1 R42.2 R43.2 U2.15(VCCR) U2.16(VCCT)
+3V3A_SFP2: C79.1 C80.1 C81.1 C84.1 C85.1 Q2.3(D) R47.2 R48.2 R49.2 R50.2 R51.2 R52.2 R56.2 R58.2 R64.2 R78.1 U7.15(VCCR) U7.16(VCCT)
+3V3S: C4.2 C5.2 P1.56(3V3S) P1.58(3V3S) P1.68(3V3S) P1.70(3V3S) P1.72(3V3S) P1.74(3V3S) R1.1
+5V: C2.2 C3.2 C44.1 C45.1 P1.1(5VA) P1.2(5VA) P1.4(5VA) P1.6(5VA) P1.8(5VA) P1.10(5VA) P1.12(5VA) P1.14(5VA) P1.16(5VA) P1.18(5VA) P1.20(5VA) R101.2 U10.6(PVDD)
GND: C1.1 C2.1 C3.1 C4.1 C5.1 C6.1 C7.1 C8.1 C9.1 C10.2 C11.2 C12.2 C13.2 C14.2 C15.2 C16.2 C17.2 C18.2 C19.2 C20.2 C21.2 C22.2 C23.2 C24.2 C25.2 C28.2 C29.1 C30.1 C32.2 C33.2 C34.1 C37.1 C39.1 C40.1 C41.1 C42.1 C44.2 C45.2 C46.2 C49.2 C50.2 C51.2 C52.2 C53.2 C62.2 C63.2 C64.2 C65.2 C66.2 C68.1 C69.2 C70.2 C71.2 C72.1 C73.2 C75.1 C77.1 C78.2 C79.2 C80.2 C81.2 C84.2 C85.2 C86.1 FB1.2 FB2.2 P1.3(GND) P1.9(GND) P1.15(GND) P1.21(GND) P1.27(GND) P1.33(GND) P1.39(GND) P1.45(GND) P1.46(GND) P1.50(GND) P1.51(GND) P1.57(GND) P1.71(GND) R6.2 R7.2 R8.2 R10.2 R17.1 R19.1 R27.2 R30.1 R32.1 R36.2 R38.1 R46.1 R57.1 R59.1 R65.1 R66.1 R69.1 R76.2 R77.2 R81.1 R82.1 R83.1 R84.1 R85.1 R90.2 R91.2 R95.1 R96.1 R100.2 R103.1 U1.4(GND) U2.1(VEET) U2.10(VEER) U2.11(VEER) U2.14(VEER) U2.17(VEET) U2.20(VEET) U3.65(PAD_GND) U4.4(GND) U4.9(EPAD) U5.65(PAD_GND) U6.4(GND) U6.9(EPAD) U7.1(VEET) U7.10(VEER) U7.11(VEER) U7.14(VEER) U7.17(VEET) U7.20(VEET) U8.6(GND) U8.15(GND) U8.19(GNDA) U10.2(GND) U10.5(PGND) U10.11(GND) X1.2(GND) X1.4(GND) X2.2(GND) X2.4(GND)
CHASSIS: C34.2 C68.2 CG1.1(SHIELD) CG1.2(SHIELD) CG1.3(SHIELD) CG1.4(SHIELD) CG1.5(SHIELD) CG1.6(SHIELD) CG1.7(SHIELD) CG1.8(SHIELD) CG1.9(SHIELD) CG1.10(SHIELD) CG1.11(SHIELD) CG1.12(SHIELD) CG1.13(SHIELD) CG1.14(SHIELD) CG1.15(SHIELD) CG1.16(SHIELD) CG1.17(SHIELD) CG1.18(SHIELD) CG1.19(SHIELD) CG1.20(SHIELD) CG2.1(SHIELD) CG2.2(SHIELD) CG2.3(SHIELD) CG2.4(SHIELD) CG2.5(SHIELD) CG2.6(SHIELD) CG2.7(SHIELD) CG2.8(SHIELD) CG2.9(SHIELD) CG2.10(SHIELD) CG2.11(SHIELD) CG2.12(SHIELD) CG2.13(SHIELD) CG2.14(SHIELD) CG2.15(SHIELD) CG2.16(SHIELD) CG2.17(SHIELD) CG2.18(SHIELD) CG2.19(SHIELD) CG2.20(SHIELD) FB1.1 FB2.1
CLK_PCIE_0N: R82.2 R86.2 U3.25(PE_CLKN)
CLK_PCIE_0N_R: R86.1 U8.8(PCIEXC0)
CLK_PCIE_0P: R83.2 R87.2 U3.26(PE_CLKP)
CLK_PCIE_0P_R: R87.1 U8.7(PCIEXT0)
CLK_PCIE_1N: R88.2 R95.2 U5.25(PE_CLKN)
CLK_PCIE_1N_R: R88.1 U8.13(PCIEXC1)
CLK_PCIE_1P: R89.2 R96.2 U5.26(PE_CLKP)
CLK_PCIE_1P_R: R89.1 U8.14(PCIEXT1)
CLK_PCIE_N: P1.53(PCIE_CLKN) R84.2 U8.3(CLK_INC)
CLK_PCIE_P: P1.55(PCIE_CLKP) R85.2 U8.2(CLK_INT)
CLKMP_IREF: R90.1 U8.18(IREF)
CLKMP_PLL_BW: R91.1 R92.2 U8.1(PLL_BW)
CLKREQ6#: P1.26(CLKREQ#) R9.2 R10.1
EEPROM_A0: R5.2 R8.1 U1.1(A0)
EEPROM_A1: R4.2 R7.1 U1.2(A1)
EEPROM_A2: R3.2 R6.1 U1.3(A2)
EXT_VCC_3V3_CMP: R104.2 U10.10(COMP)
EXT_VCC_3V3_FB: C74.2 R102.1 R103.2 U10.9(FB)
EXT_VCC_3V3_LX: L8.1 U10.3(LX1) U10.4(LX2)
EXT_VCC_3V3_RC: C72.2 R104.1
EXT_VCC_3V3_RT: R100.1 U10.1(SHDN/RT)
EXT_VCC_3V3_VDD: R101.1 U10.7(VDD)
LAN_CBOT: C31.1 U3.37(CBOT)
LAN_CBOT_2: C48.1 U5.37(CBOT)
LAN_CTOP: C31.2 U3.40(CTOP)
LAN_CTOP_2: C48.2 U5.40(CTOP)
LAN_DEV_OFF#: R44.2 U3.28(DEV_OFF_N)
LAN_DEV_OFF#_2: R79.2 U5.28(DEV_OFF_N)
LAN_JTAG_CLK: R20.2 U3.19(JTAG_CLK)
LAN_JTAG_CLK_2: R60.2 U5.19(JTAG_CLK)
LAN_JTAG_TDI: R22.2 U3.29(JTAG_TDI)
LAN_JTAG_TDI_2: R62.2 U5.29(JTAG_TDI)
LAN_JTAG_TDO: R23.2 U3.4(JTAG_TDO)
LAN_JTAG_TDO_2: R63.2 U5.4(JTAG_TDO)
LAN_JTAG_TMS: R21.2 U3.18(JTAG_TMS)
LAN_JTAG_TMS_2: R61.2 U5.18(JTAG_TMS)
LAN_LED0: D1.1(ANODE1) U3.31(LED0)
LAN_LED0_2: D2.1(ANODE1) U5.31(LED0)
LAN_LED1: DS2.CATHODE U3.30(LED1)
LAN_LED1_2: DS4.CATHODE U5.30(LED1)
LAN_LED2: D1.2(ANODE2) U3.33(LED2)
LAN_LED2_2: D2.2(ANODE2) U5.33(LED2)
LAN_NCSI_PD1: R30.2 U3.2(NC_SI_CLK_IN)
LAN_NCSI_PD1_2: R65.2 U5.2(NC_SI_CLK_IN)
LAN_NCSI_PD2: R32.2 U3.3(NC_SI_CRS_DV)
LAN_NCSI_PD2_2: R66.2 U5.3(NC_SI_CRS_DV)
LAN_NCSI_PD3: R38.2 U3.7(NC_SI_TX_EN)
LAN_NCSI_PD3_2: R69.2 U5.7(NC_SI_TX_EN)
LAN_NCSI_PU1: R34.2 U3.6(NC_SI_RXD0)
LAN_NCSI_PU1_2: R67.2 U5.6(NC_SI_RXD0)
LAN_NCSI_PU2: R35.2 U3.5(NC_SI_RXD1)
LAN_NCSI_PU2_2: R68.2 U5.5(NC_SI_RXD1)
LAN_NCSI_PU3: R37.2 U3.9(NC_SI_TXD0)
LAN_NCSI_PU3_2: R70.2 U5.9(NC_SI_TXD0)
LAN_NCSI_PU4: R39.2 U3.8(NC_SI_TXD1)
LAN_NCSI_PU4_2: R71.2 U5.8(NC_SI_TXD1)
LAN_PWR_GOOD: R40.1 U3.1(LAN_PWR_GOOD)
LAN_PWR_GOOD_2: R72.1 U5.1(LAN_PWR_GOOD)
LAN_RSET: R36.1 U3.48(RSET)
LAN_RSET_2: R77.1 U5.48(RSET)
LAN_SER_N: U2.12(RD-) U3.49(SER_N)
LAN_SER_N_2: U5.49(SER_N) U7.12(RD-)
LAN_SER_P: U2.13(RD+) U3.50(SER_P)
LAN_SER_P_2: U5.50(SER_P) U7.13(RD+)
LAN_SET_N: U2.19(TD-) U3.52(SET_N)
LAN_SET_N_2: U5.52(SET_N) U7.19(TD-)
LAN_SET_P: U2.18(TD+) U3.53(SET_P)
LAN_SET_P_2: U5.53(SET_P) U7.18(TD+)
LAN_SFP_I2C_CLK: R13.1 U2.5(SCL) U3.55(SFP_I2C_CLK)
LAN_SFP_I2C_CLK_2: R49.1 U5.55(SFP_I2C_CLK) U7.5(SCL)
LAN_SFP_I2C_DATA: R14.1 U2.4(SDA) U3.57(SFP_I2C_DATA)
LAN_SFP_I2C_DATA_2: R50.1 U5.57(SFP_I2C_DATA) U7.4(SDA)
LAN_SFP_MOD_ABS: R12.1 U2.6(MOD-ABS) U3.63(SDP0)
LAN_SFP_MOD_ABS_2: R48.1 U5.63(SDP0) U7.6(MOD-ABS)
LAN_SFP_PWR: Q1.1(G) U3.60(SDP3)
LAN_SFP_PWR_2: Q2.1(G) U5.60(SDP3)
LAN_SFP_RX_LOS: R24.1 U2.8(RX_LOS) U3.54(SRDS_SIG_DET)
LAN_SFP_RX_LOS_2: R64.1 U5.54(SRDS_SIG_DET) U7.8(RX_LOS)
LAN_SFP_TX_DISABLE: R27.1 U2.3(TX_DISABLE) U3.61(SDP1)
LAN_SFP_TX_DISABLE_2: R76.1 U5.61(SDP1) U7.3(TX_DISABLE)
LAN_SFP_TX_FAULT: R15.1 U2.2(TX_FAULT) U3.62(SDP2)
LAN_SFP_TX_FAULT_2: R52.1 U5.62(SDP2) U7.2(TX_FAULT)
LAN_SPI_CLK: R28.1 U3.13(NVM_CLK)
LAN_SPI_CLK_2: R75.1 U5.13(NVM_CLK)
LAN_SPI_CLK_R: R28.2 U4.6(SCK)
LAN_SPI_CLK_R_2: R75.2 U6.6(SCK)
LAN_SPI_CS#: R29.1 U3.15(NVM_CS_N)
LAN_SPI_CS#_2: R55.1 U5.15(NVM_CS_N)
LAN_SPI_CS#_R: R29.2 U4.1(CS#)
LAN_SPI_CS#_R_2: R55.2 U6.1(CS#)
LAN_SPI_HOLD#: R33.1 U4.7(HOLD#)
LAN_SPI_HOLD#_2: R74.1 U6.7(HOLD#)
LAN_SPI_SI: R26.1 U3.12(NVM_SI)
LAN_SPI_SI_2: R54.1 U5.12(NVM_SI)
LAN_SPI_SI_R: R26.2 U4.5(DI)
LAN_SPI_SI_R_2: R54.2 U6.5(DI)
LAN_SPI_SO: R25.1 U3.14(NVM_SO)
LAN_SPI_SO_2: R53.1 U5.14(NVM_SO)
LAN_SPI_SO_R: R25.2 R45.1 R46.2 U4.2(DO)
LAN_SPI_SO_R_2: R53.2 R80.1 R81.2 U6.2(DO)
LAN_SPI_WP#: R31.1 U4.3(WP#)
LAN_SPI_WP#_2: R73.1 U6.3(WP#)
LAN_XTAL1: C30.2 U3.46(XTAL1) X1.3
LAN_XTAL1_2: C77.2 U5.46(XTAL1) X2.3
LAN_XTAL2: C29.2 U3.45(XTAL2) X1.1
LAN_XTAL2_2: C75.2 U5.45(XTAL2) X2.1
LED1_L: DS1.ANODE R43.1
LED2_R: DS2.ANODE R42.1
LED3_L: DS3.ANODE R47.1
LED4_R: DS4.ANODE R51.1
PCIE0_RXN: C27.1 P1.41(PCIE_RX0N)
PCIE0_RXN_C: C27.2 U3.20(PE_TN)
PCIE0_RXP: C26.1 P1.43(PCIE_RX0P)
PCIE0_RXP_C: C26.2 U3.21(PE_TP)
PCIE0_TXN: P1.47(PCIE_TX0N) U3.24(PE_RP)
PCIE0_TXP: P1.49(PCIE_TX0P) U3.23(PE_RN)
PCIE1_RXN: C83.1 P1.29(PCIE_RX1N)
PCIE1_RXN_C: C83.2 U5.20(PE_TN)
PCIE1_RXP: C82.1 P1.31(PCIE_RX1P)
PCIE1_RXP_C: C82.2 U5.21(PE_TP)
PCIE1_TXN: P1.35(PCIE_TX1N) U5.23(PE_RN)
PCIE1_TXP: P1.37(PCIE_TX1P) U5.24(PE_RP)
PE_WAKE#: P1.22(PCIE_WAKE#) R11.2 U3.16(PE_WAKE_N) U5.16(PE_WAKE_N)
PLTRST#: P1.24(RESET#) U3.17(PE_RST_N) U5.17(PE_RST_N)
SATAXPCIE0: P1.36(PCIE_SATA#) R111.2
SFP_RS0: R18.1 R19.2 U2.7(RS0)
SFP_RS0_2: R58.1 R59.2 U7.7(RS0)
SFP_RS1: R16.1 R17.2 U2.9(RS1)
SFP_RS1_2: R56.1 R57.2 U7.9(RS1)
SMB_ALERT#: P1.44(SMB_ALERT#) U3.35(SMB_ALRT_N) U5.35(SMB_ALRT_N)
SMB_CLK: P1.48(SMB_CLK) R94.1 U1.6(SCL) U3.34(SMB_CLK) U5.34(SMB_CLK)
SMB_CLK_CLKMP: R94.2 U8.11(SMBCLK)
SMB_DATA: P1.42(SMB_DATA) R93.1 U1.5(SDA) U3.36(SMB_DAT) U5.36(SMB_DAT)
SMB_DATA_CLKMP: R93.2 U8.10(SMBDAT)
N16687308: D1.3(CATHODE) DS1.CATHODE
N16688070: D2.3(CATHODE) DS3.CATHODE

Not connected (* = marked no-connect by the designer): P1 5(PCIE_RX3N)* 7(PCIE_RX3P)* 11(PCIE_TX3N)* 13(PCIE_TX3P)* 17(PCIE_RX2N)* 19(PCIE_RX2P)* 23(PCIE_TX2N)* 25(PCIE_TX2P)* 30(RIBBON_ID1)* 32(RIBBON_ID2)* 34(RIBBON_ID3)* 38(RSVD)* 40(RIBBON_ID4)* 52(Diff._RSVD1_N)* 54(Diff._RSVD1_P)* 67(Diff._RSVD2_N)* 69(Diff._RSVD2_P)* 73(USB2_N)* 75(USB2_P)*; U1 7(WP)*; U3 22(NC3)* 43(NC_SI_ARB_IN)* 44(NC_SI_ARB_OUT)* 56(NC1)* 58(NC2)*; U5 22(NC3)* 43(NC_SI_ARB_IN)* 44(NC_SI_ARB_OUT)* 56(NC1)* 58(NC2)*; U8 4(vCLKREQ0#)* 17(vCLKREQ1#)*; U10 8(PGOOD)*

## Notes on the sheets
sheet 1
- FT.W-OPLN2
- EEPROM
- A0 and A1 are NC in 24C08
- NOP
- SMB:0x54
- NOP
- NOP
sheet 2
- PCI Clock
- Bulk #4
- The PCI clock disable.
- NOP
- The PCI clock enable.
- SATA / PCIe
- High -> PCIe
- NOP
- CLOCK Multiplier
- Internal 120K PD
- EXT_VCC_3V3 - 3.3V,1.5A
- Vout=0.8(1+R1/R2)
- Internal 120K PD
- NOP
- R1
- 0.8V
- R2
- NOP
sheet 3
- LAN I210IS
- DNP
- DNP
- RateSelect strap
- DNP
- I210IS
- DNP
- Flash security
  is disabled
  when the
  pin is pulled
  low.
- 33R near  Flash
- should be
  ESR<50ohm
- should be
  39nF
- DNP
- STITCHING CAPACITORS
- SFP CAGE
- LAN SFP LINK LEDs
sheet 4
- LAN I210IS
- DNP
- DNP
- RateSelect strap
- DNP
- I210IS
- DNP
- Flash security
  is disabled
  when the
  pin is pulled
  low.
- 33R near  Flash
- should be
  ESR<50ohm
- DNP
- should be
  39nF
- SFP CAGE
- LAN SFP LINK LEDs
